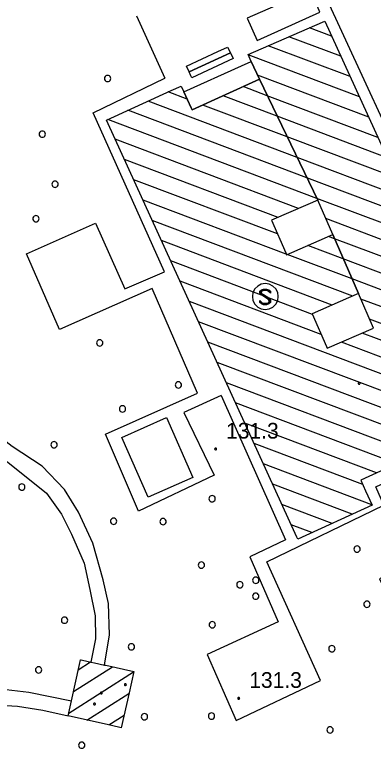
# Model space of a CAD drawing. Extents: x 513373 to 514978, y 5038576 to 5040180.
# Drawn here: x 513457.4 to 513491.5, y 5038720.6 to 5038790.7 of the extents above; entities that cross this region are included whole.
import ezdxf

# ---------------------------------------------------------------- set-up
doc = ezdxf.new("R2010")
doc.units = 0
for name, color, linetype in [('3010204', 7, 'Continuous'), ('3030201', 7, 'Continuous'), ('B12210', 7, 'Continuous'), ('C1131', 7, 'Continuous'), ('C12211', 7, 'Continuous'), ('C211113', 7, 'Continuous'), ('C211123', 7, 'Continuous'), ('CAMP_C12211', 7, 'Continuous'), ('Default', 7, 'Continuous'), ('F12107', 7, 'Continuous'), ('F12131', 7, 'Continuous'), ('F12132', 7, 'Continuous'), ('G4315', 7, 'Continuous'), ('TOP920', 7, 'Continuous')]:
    doc.layers.add(name, color=color, linetype=linetype)

# ---------------------------------------------------------------- blocks, each defined once
blk = doc.blocks.new('CAMP_28E5D3F1')
at = {"layer": 'CAMP_C12211'}
for p, q in [((1.849, 21.59), (-0.251, 22.384)), ((2.732, 19.653), (-2.224, 21.526)), ((3.615, 17.716), (-4.197, 20.668)), ((4.498, 15.779), (-6.101, 19.784)), ((5.38, 13.842), (-5.217, 17.846)), ((-11.933, 15.574), (-13.73, 16.252)), ((-4.284, 15.89), (-6.585, 16.76)), ((-3.338, 13.929), (-8.508, 15.883)), ((6.263, 11.905), (-4.284, 15.89)), ((-1.447, 10.007), (-15.653, 15.376)), ((-2.392, 11.968), (-10.432, 15.006)), ((-0.501, 8.047), (-17.577, 14.499)), ((0.444, 6.086), (-19.5, 13.622)), ((7.146, 9.968), (-3.338, 13.929)), ((8.029, 8.03), (-2.392, 11.968)), ((-1.298, 5.141), (-18.778, 11.746)), ((-3.263, 4.28), (-17.895, 9.809)), ((8.912, 6.093), (-1.447, 10.007)), ((-3.32, 2.698), (-17.012, 7.872)), ((9.794, 4.156), (-0.501, 8.047)), ((-2.478, 0.776), (-16.129, 5.934)), ((10.677, 2.219), (0.444, 6.086)), ((3.869, -3.226), (-15.247, 3.997)), ((11.56, 0.282), (1.294, 4.161)), ((2.133, 2.241), (1.544, 2.463)), ((12.443, -1.655), (2.133, 2.241)), ((1.904, -4.087), (-14.364, 2.06)), ((2.962, 0.324), (-0.421, 1.602)), ((3.791, -1.593), (-2.387, 0.742)), ((0.01, -4.975), (-13.481, 0.123)), ((13.326, -3.592), (2.962, 0.324)), ((0.852, -6.896), (-12.598, -1.814)), ((14.208, -5.529), (3.791, -1.593)), ((18.623, -15.215), (-11.716, -3.751)), ((15.091, -7.466), (4.624, -3.511)), ((15.974, -9.403), (5.466, -5.433)), ((18.961, -16.946), (-10.833, -5.688)), ((16.857, -11.341), (4.746, -6.764)), ((17.038, -17.823), (-9.95, -7.625)), ((17.74, -13.278), (2.78, -7.625)), ((15.114, -18.7), (-9.067, -9.562)), ((9.957, -18.354), (-8.184, -11.499)), ((8.034, -19.231), (-7.302, -13.436)), ((6.11, -20.108), (-6.419, -15.374)), ((4.812, -21.221), (-5.536, -17.311)), ((5.695, -23.158), (-4.653, -19.248)), ((13.19, -19.576), (11.759, -19.035)), ((3.82, -24.053), (-3.77, -21.185)), ((1.896, -24.93), (-2.888, -23.122)), ((-0.027, -25.806), (-2.005, -25.059))]:
    blk.add_line(p, q, dxfattribs=at)
blk = doc.blocks.new('CAMP_5C9A8D68')
at = {"layer": 'CAMP_C12211'}
for p, q in [((-2.124, 2.205), (-0.954, 2.948)), ((-2.581, 0.139), (1.122, 2.489)), ((-3.038, -1.928), (3.154, 2.002)), ((-1.296, -2.599), (2.697, -0.065)), ((0.78, -3.058), (2.24, -2.131))]:
    blk.add_line(p, q, dxfattribs=at)
blk = doc.blocks.new('CAMP_161D2596')
at = {"layer": 'CAMP_C12211'}
for p, q in [((9.387, 16.638), (8.639, 16.921)), ((10.277, 14.698), (6.723, 16.041)), ((11.168, 12.758), (4.807, 15.162)), ((12.058, 10.818), (2.891, 14.283)), ((12.949, 8.878), (0.975, 13.403)), ((13.84, 6.938), (-0.699, 12.432)), ((14.73, 4.998), (0.191, 10.492)), ((15.621, 3.058), (1.082, 8.552)), ((-4.577, 7.483), (-6.827, 8.334)), ((-3.686, 5.543), (-8.743, 7.454)), ((16.511, 1.118), (1.973, 6.612)), ((17.487, -4.061), (-9.485, 6.131)), ((2.939, -0.167), (-10.195, 4.796)), ((-0.758, 4.437), (-1.414, 4.685)), ((17.402, -0.822), (2.864, 4.672)), ((1.913, -1.383), (-12.112, 3.916)), ((18.292, -2.762), (1.219, 3.69)), ((2.738, -3.298), (-14.028, 3.037)), ((0.823, -4.178), (-15.944, 2.157)), ((1.657, -6.097), (-17.86, 1.278)), ((2.547, -8.037), (-19.72, 0.377)), ((15.571, -4.941), (5.534, -1.148)), ((3.138, -9.864), (-18.829, -1.563)), ((13.655, -5.82), (6.425, -3.088)), ((1.222, -10.743), (-17.939, -3.503)), ((-2.28, -11.023), (-17.048, -5.443)), ((11.739, -6.7), (7.315, -5.028)), ((9.823, -7.579), (8.206, -6.968)), ((-4.196, -11.903), (-16.158, -7.383)), ((-6.112, -12.782), (-15.267, -9.323)), ((-8.028, -13.662), (-14.377, -11.263)), ((-0.694, -11.623), (-1.47, -11.33)), ((-9.944, -14.541), (-13.486, -13.203)), ((-11.86, -15.421), (-12.596, -15.143))]:
    blk.add_line(p, q, dxfattribs=at)
blk = doc.blocks.new('08020400')
at = {"layer": 'Default'}
for p, q in [((-0.086, 0.028), (-0.09, 0)), ((-0.09, 0), (-0.086, -0.028)), ((-0.073, 0.053), (-0.086, 0.028)), ((-0.053, 0.073), (-0.073, 0.053)), ((-0.028, 0.086), (-0.053, 0.073)), ((0, 0.09), (-0.028, 0.086)), ((0.028, 0.086), (0, 0.09)), ((0.053, 0.073), (0.028, 0.086)), ((0.073, 0.053), (0.053, 0.073)), ((0.086, 0.028), (0.073, 0.053)), ((0.09, 0), (0.086, 0.028)), ((0.086, -0.028), (0.09, 0)), ((-0.086, -0.028), (-0.073, -0.053)), ((-0.073, -0.053), (-0.053, -0.073)), ((-0.053, -0.073), (-0.028, -0.086)), ((-0.028, -0.086), (0, -0.09)), ((0, -0.09), (0.028, -0.086)), ((0.028, -0.086), (0.053, -0.073)), ((0.053, -0.073), (0.073, -0.053)), ((0.073, -0.053), (0.086, -0.028))]:
    blk.add_line(p, q, dxfattribs=at)
blk = doc.blocks.new('NSIMB25')
at = {"layer": 'Default'}
for p, q in [((-0.086, 0.028), (-0.09, 0)), ((-0.09, 0), (-0.086, -0.028)), ((-0.073, 0.053), (-0.086, 0.028)), ((-0.053, 0.073), (-0.073, 0.053)), ((-0.028, 0.086), (-0.053, 0.073)), ((0, 0.09), (-0.028, 0.086)), ((0.028, 0.086), (0, 0.09)), ((0.053, 0.073), (0.028, 0.086)), ((0.073, 0.053), (0.053, 0.073)), ((0.086, 0.028), (0.073, 0.053)), ((0.09, 0), (0.086, 0.028)), ((0.086, -0.028), (0.09, 0)), ((-0.086, -0.028), (-0.073, -0.053)), ((-0.073, -0.053), (-0.053, -0.073)), ((-0.053, -0.073), (-0.028, -0.086)), ((-0.028, -0.086), (0, -0.09)), ((0, -0.09), (0.028, -0.086)), ((0.028, -0.086), (0.053, -0.073)), ((0.053, -0.073), (0.073, -0.053)), ((0.073, -0.053), (0.086, -0.028))]:
    blk.add_line(p, q, dxfattribs=at)
blk = doc.blocks.new('05010100')
at = {"layer": 'Default'}
for p, q in [((-0.143, 0.046), (-0.15, 0)), ((-0.15, 0), (-0.143, -0.046)), ((-0.121, 0.088), (-0.143, 0.046)), ((-0.088, 0.121), (-0.121, 0.088)), ((-0.046, 0.143), (-0.088, 0.121)), ((0, 0.15), (-0.046, 0.143)), ((0.046, 0.143), (0, 0.15)), ((0.088, 0.121), (0.046, 0.143)), ((0.121, 0.088), (0.088, 0.121)), ((0.143, 0.046), (0.121, 0.088)), ((0.15, 0), (0.143, 0.046)), ((0.143, -0.046), (0.15, 0)), ((-0.143, -0.046), (-0.121, -0.088)), ((-0.121, -0.088), (-0.088, -0.121)), ((-0.088, -0.121), (-0.046, -0.143)), ((-0.046, -0.143), (0, -0.15)), ((0, -0.15), (0.046, -0.143)), ((0.046, -0.143), (0.088, -0.121)), ((0.088, -0.121), (0.121, -0.088)), ((0.121, -0.088), (0.143, -0.046))]:
    blk.add_line(p, q, dxfattribs=at)
blk = doc.blocks.new('03030201')
at = {"layer": 'Default'}
for p, q in [((-1.001, 0.728), (-1.177, 0.382)), ((-0.728, 1.001), (-1.001, 0.728)), ((-0.382, 1.177), (-0.728, 1.001)), ((0, 1.237), (-0.382, 1.177)), ((-0.368, 0.643), (-0.158, 0.718)), ((-0.158, 0.718), (0.127, 0.718)), ((0.382, 1.177), (0, 1.237)), ((0.127, 0.718), (0.337, 0.643)), ((0.728, 1.001), (0.382, 1.177)), ((1.001, 0.728), (0.728, 1.001)), ((1.177, 0.382), (1.001, 0.728)), ((-1.177, 0.382), (-1.238, 0)), ((-1.238, 0), (-1.177, -0.382)), ((-0.518, 0.508), (-0.368, 0.643)), ((-0.518, 0.358), (-0.518, 0.508)), ((-0.443, 0.223), (-0.518, 0.358)), ((-0.333, 0.584), (-0.451, 0.478)), ((-0.451, 0.478), (-0.451, 0.376)), ((-0.451, 0.376), (-0.389, 0.265)), ((-0.368, 0.148), (-0.443, 0.223)), ((-0.389, 0.265), (-0.326, 0.201)), ((-0.298, 0.526), (-0.383, 0.448)), ((-0.383, 0.448), (-0.383, 0.394)), ((-0.383, 0.394), (-0.335, 0.306)), ((0.148, -0.186), (-0.368, 0.148)), ((-0.335, 0.306), (-0.287, 0.257)), ((-0.147, 0.651), (-0.333, 0.584)), ((-0.326, 0.201), (0.183, -0.128)), ((-0.135, 0.583), (-0.298, 0.526)), ((-0.287, 0.257), (-0.18, 0.198)), ((-0.18, 0.198), (0.337, -0.137)), ((0.115, 0.651), (-0.147, 0.651)), ((0.103, 0.583), (-0.135, 0.583)), ((0.266, 0.526), (0.103, 0.583)), ((0.301, 0.584), (0.115, 0.651)), ((0.487, 0.327), (0.266, 0.526)), ((0.487, 0.418), (0.301, 0.584)), ((0.337, 0.643), (0.487, 0.508)), ((0.487, 0.508), (0.487, 0.327)), ((1.238, 0), (1.177, 0.382)), ((1.177, -0.382), (1.238, 0)), ((-1.177, -0.382), (-1.001, -0.728)), ((-0.518, -0.39), (-0.298, -0.588)), ((-0.518, -0.572), (-0.518, -0.39)), ((-0.333, -0.647), (-0.518, -0.481)), ((-0.368, -0.707), (-0.518, -0.572)), ((-0.147, -0.714), (-0.333, -0.647)), ((-0.298, -0.588), (-0.135, -0.647)), ((-0.135, -0.647), (0.103, -0.647)), ((0.103, -0.647), (0.266, -0.588)), ((0.301, -0.647), (0.115, -0.714)), ((0.254, -0.245), (0.148, -0.186)), ((0.183, -0.128), (0.295, -0.191)), ((0.302, -0.293), (0.254, -0.245)), ((0.266, -0.588), (0.352, -0.512)), ((0.295, -0.191), (0.357, -0.253)), ((0.419, -0.542), (0.301, -0.647)), ((0.352, -0.382), (0.302, -0.293)), ((0.337, -0.137), (0.412, -0.212)), ((0.487, -0.572), (0.337, -0.707)), ((0.352, -0.512), (0.352, -0.382)), ((0.357, -0.253), (0.419, -0.364)), ((0.412, -0.212), (0.487, -0.347)), ((0.419, -0.364), (0.419, -0.542)), ((0.487, -0.347), (0.487, -0.572)), ((1.001, -0.728), (1.177, -0.382)), ((-1.001, -0.728), (-0.728, -1.001)), ((-0.728, -1.001), (-0.382, -1.177)), ((-0.382, -1.177), (0, -1.238)), ((-0.158, -0.782), (-0.368, -0.707)), ((0.127, -0.782), (-0.158, -0.782)), ((0.115, -0.714), (-0.147, -0.714)), ((0, -1.238), (0.382, -1.177)), ((0.337, -0.707), (0.127, -0.782)), ((0.382, -1.177), (0.728, -1.001)), ((0.728, -1.001), (1.001, -0.728))]:
    blk.add_line(p, q, dxfattribs=at)
blk = doc.blocks.new('A$C3704598A')
at = {"layer": '3010204'}
for points in [[(123.244, -607.886), (113.934, -587.68), (116.864, -587.123), (119.4, -586.47), (121.933, -585.805)], [(112.864, -587.88), (109.912, -588.32), (106.487, -589.801), (107.445, -591.945), (113.411, -589.231), (112.864, -587.88)], [(95.927, -589.59), (98.636, -595.534)], [(104.013, -625.817), (100.447, -627.437), (103.325, -633.428), (96.122, -636.853), (92.977, -629.513), (101.739, -625.59), (97.409, -615.594), (88.601, -619.517), (85.455, -612.294), (92.026, -609.375), (94.808, -615.643), (98.583, -614.002), (91.786, -598.854), (98.636, -595.534)], [(92.872, -651.548), (93.342, -648.667), (93.254, -645.665), (92.735, -643.42), (91.755, -639.917), (90.412, -636.949), (89.063, -634.787), (86.93, -632.574), (84.077, -630.692), (81.606, -628.767), (79.606, -626.735), (81.777, -626.976), (82.21, -615.083), (80.486, -614.89), (80.767, -607.902), (76.557, -607.577), (76.323, -608.852), (75.897, -608.916), (75.451, -608.621), (74.008, -607.389)], [(74.367, -610.967), (74.748, -612.446), (74.884, -615.091), (75.152, -617.916), (74.879, -621.275), (74.829, -621.857), (74.979, -622.777), (75.905, -624.599), (77.632, -626.965), (79.387, -628.884), (82.571, -631.352), (84.775, -633.072), (87.335, -635.154), (88.775, -637.137), (89.745, -639.072), (90.955, -641.837), (91.473, -644.351), (91.99, -646.864), (92.017, -649.038), (91.58, -651.262)], [(104.013, -625.817), (110.125, -639.589), (106.745, -641.211), (109.435, -647.409), (102.653, -650.535), (105.434, -656.85), (113.453, -653.038), (108.366, -641.711), (119.508, -636.299), (118.733, -634.551), (123.464, -632.337), (126.843, -639.562), (119.08, -643.308), (121.773, -649.111), (130.306, -644.861)], [(74.514, -654.017), (76.206, -653.794), (78.605, -653.657), (80.979, -653.698), (82.972, -653.804), (85.68, -654.14), (89.722, -654.969)], [(74.899, -655.556), (76.194, -655.318), (79.153, -655.162), (81.929, -655.319), (84.572, -655.475), (86.989, -655.853), (89.405, -656.404)]]:
    blk.add_lwpolyline(points, dxfattribs=at)
at = {"layer": 'B12210'}
blk.add_lwpolyline([(105.132, -593.668), (101.206, -595.485), (101.117, -595.294), (100.949, -594.93), (100.692, -594.375), (103.683, -592.991), (104.618, -592.558), (104.875, -593.114)], close=True, dxfattribs=at)
at = {"layer": 'C1131'}
blk.add_lwpolyline([(122.936, -631.318), (117.297, -633.889), (117.772, -634.93), (118.392, -636.291), (118.378, -636.297), (111.299, -639.523), (111.214, -639.336), (93.072, -599.527), (99.245, -596.713), (100.184, -596.285), (100.436, -596.839), (101.136, -598.375), (101.221, -598.562), (107.64, -595.636), (113.199, -607.164), (112.251, -607.579), (108.79, -609.095), (110.155, -612.211), (110.231, -612.385), (114.64, -610.455), (117.079, -616.094), (116.133, -616.508), (112.67, -618.026), (114.036, -621.141), (114.112, -621.316), (118.521, -619.385), (117.079, -616.094), (114.64, -610.455), (113.199, -607.164), (107.64, -595.636), (106.864, -593.935), (106.56, -593.268), (112.936, -590.496), (113.882, -590.085), (132.016, -629.876)], dxfattribs=at)
blk.add_lwpolyline([(91.58, -651.262), (91.923, -651.337), (92.873, -651.545), (92.991, -651.574), (95.665, -652.165), (95.216, -654.198), (94.48, -657.526), (93.556, -657.322), (89.405, -656.404), (89.72, -654.979), (90.492, -651.488), (90.59, -651.043), (90.645, -651.055), (91.32, -651.205)], close=True, dxfattribs=at)
at = {"layer": 'C12211'}
blk.add_lwpolyline([(122.936, -631.318), (117.297, -633.889), (117.772, -634.93), (118.392, -636.291), (118.378, -636.297), (111.299, -639.523), (111.214, -639.336), (93.072, -599.527), (99.245, -596.713), (100.184, -596.285), (100.436, -596.839), (101.136, -598.375), (101.221, -598.562), (107.64, -595.636), (113.199, -607.164), (112.251, -607.579), (108.79, -609.095), (110.155, -612.211), (110.231, -612.385), (114.64, -610.455), (117.079, -616.094), (116.133, -616.508), (112.67, -618.026), (114.036, -621.141), (114.112, -621.316), (118.521, -619.385), (117.079, -616.094), (114.64, -610.455), (113.199, -607.164), (107.64, -595.636), (106.864, -593.935), (106.56, -593.268), (112.936, -590.496), (113.882, -590.085), (132.016, -629.876)], dxfattribs=at)
blk.add_lwpolyline([(91.58, -651.262), (91.923, -651.337), (92.873, -651.545), (92.991, -651.574), (95.665, -652.165), (95.216, -654.198), (94.48, -657.526), (93.556, -657.322), (89.405, -656.404), (89.72, -654.979), (90.492, -651.488), (90.59, -651.043), (90.645, -651.055), (91.32, -651.205)], close=True, dxfattribs=at)
at = {"layer": 'C211113'}
for points in [[(100.436, -596.839), (105.924, -594.36), (106.864, -593.935), (107.64, -595.636), (101.221, -598.562), (101.136, -598.375)], [(98.783, -627.933), (101.293, -633.634), (97.03, -635.511), (94.527, -629.825)]]:
    blk.add_lwpolyline(points, close=True, dxfattribs=at)
at = {"layer": 'C211123'}
for points in [[(104.875, -593.114), (100.949, -594.93), (100.692, -594.375), (103.683, -592.991), (104.618, -592.558)], [(105.132, -593.668), (101.206, -595.485), (101.117, -595.294), (100.949, -594.93), (104.875, -593.114)]]:
    blk.add_lwpolyline(points, close=True, dxfattribs=at)
at = {"layer": '3030201'}
blk.add_blockref('03030201', (108.208, -616.375), dxfattribs=at)
at = {"layer": 'CAMP_C12211'}
for name, p in [('CAMP_161D2596', (72.401, -575.381)), ('CAMP_28E5D3F1', (112.682, -613.099)), ('CAMP_5C9A8D68', (92.503, -654.203))]:
    blk.add_blockref(name, p, dxfattribs=at)
at = {"layer": 'F12107'}
for p in [(103.467, -630.933), (105.675, -654.728)]:
    blk.add_blockref('08020400', p, dxfattribs=at)
at = {"layer": 'F12131'}
blk.add_blockref('NSIMB25', (91.922, -655.265), dxfattribs=at)
at = {"layer": 'F12132'}
for p in [(117.155, -624.651), (94.872, -653.43), (92.58, -654.218)]:
    blk.add_blockref('NSIMB25', p, dxfattribs=at)
at = {"layer": 'G4315', "xscale": 2, "yscale": 2}
for p in [(93.17, -595.564), (86.951, -600.877), (88.159, -605.654), (86.345, -608.944), (92.424, -620.803), (99.921, -624.818), (94.594, -627.104), (88.066, -630.519), (84.999, -634.557), (103.138, -635.679), (93.749, -637.824), (98.462, -637.862), (116.957, -640.482), (102.112, -642.009), (107.301, -643.459), (105.781, -643.88), (107.289, -644.976), (117.89, -645.745), (89.068, -647.267), (103.15, -647.705), (95.44, -649.81), (114.551, -649.997), (86.592, -652.014), (103.079, -656.426), (96.687, -656.483), (114.38, -657.743), (90.706, -659.198)]:
    blk.add_blockref('05010100', p, dxfattribs=at)
at = {"layer": 'TOP920'}
for p in [(104.467, -629.933), (106.675, -653.728)]:
    blk.add_text('131.3', height=1.5, dxfattribs=at).set_placement(p)

msp = doc.modelspace()

# ---------------------------------------------------------------- block references
at = {"layer": 'Default'}
msp.add_blockref('A$C3704598A', (513373.046, 5039380.14), dxfattribs=at)

doc.saveas('drawing.dxf')
